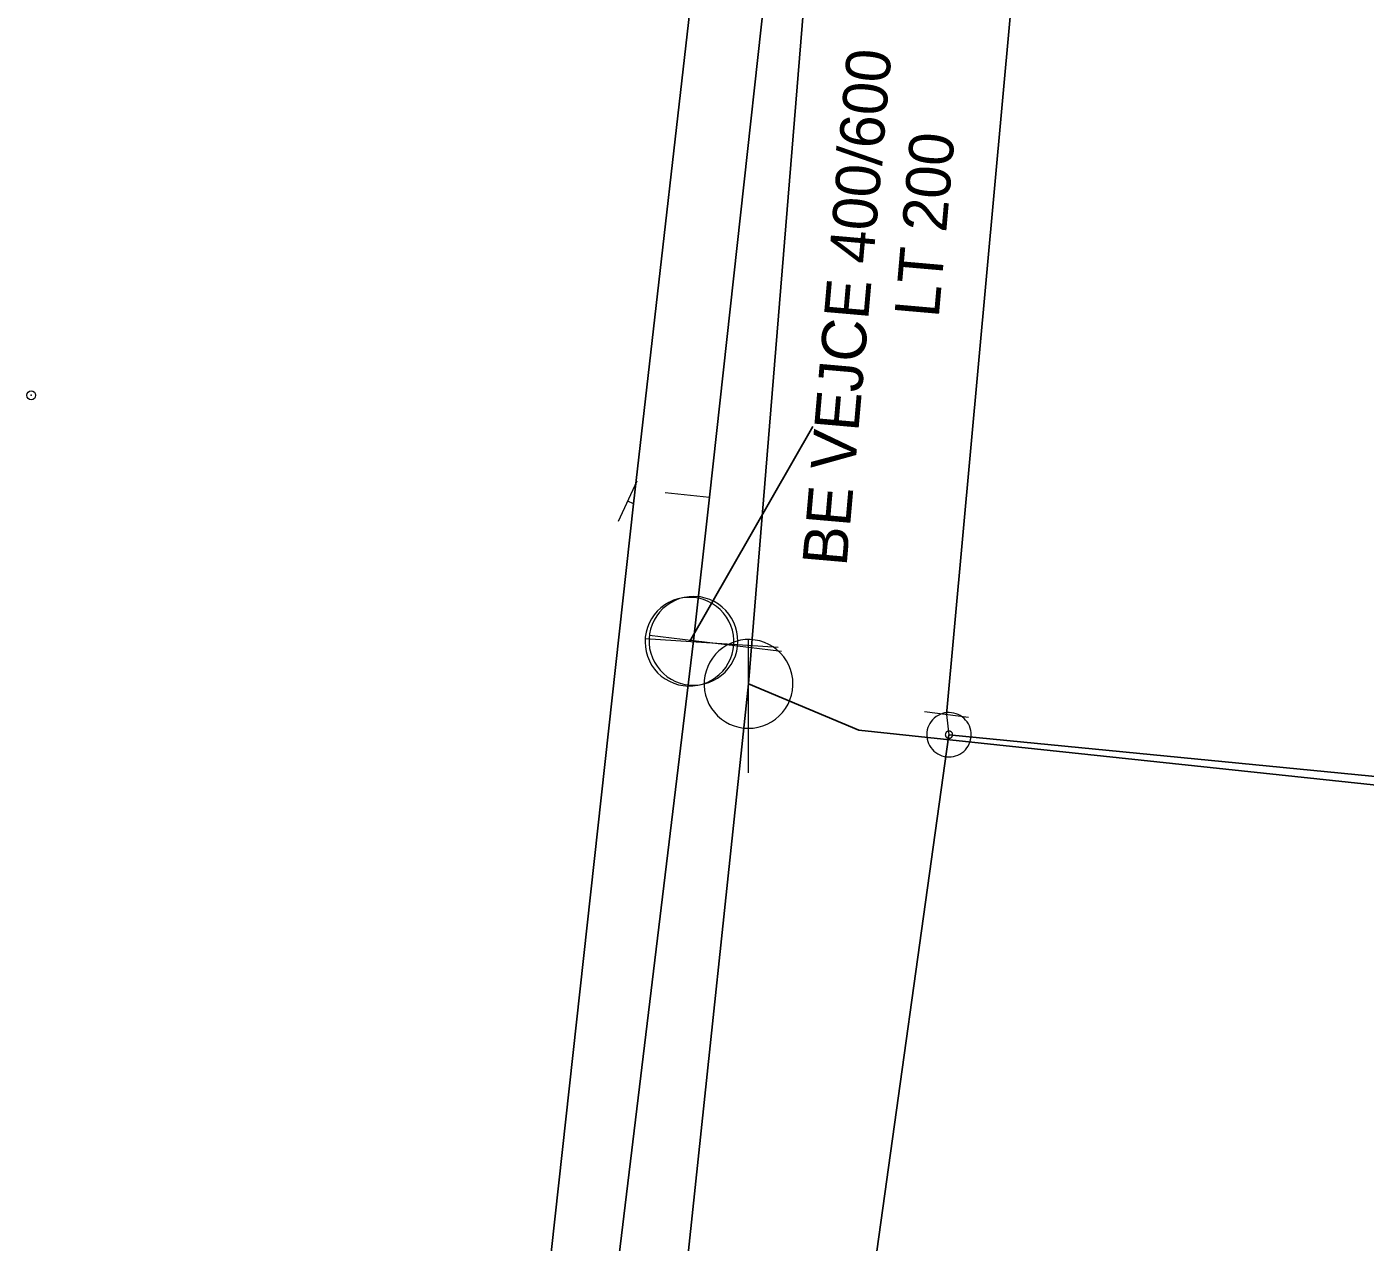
# Model space of a CAD drawing. Extents: x -783064 to -782702, y -1007904 to -1007145.
# Drawn here: x -782825.83 to -782795.69, y -1007679.86 to -1007652.48 of the extents above; entities that cross this region are included whole.
import ezdxf

# ---------------------------------------------------------------- set-up
doc = ezdxf.new("R2010")
doc.units = 0
doc.header["$LTSCALE"] = 0.4
doc.header["$PDMODE"] = 32
doc.header["$PDSIZE"] = 0.2
for name, color, linetype, lineweight in [('1', 7, 'Continuous', 13), ('11', 7, 'Continuous', 13), ('14', 7, 'Continuous', 13), ('17', 7, 'Continuous', 25), ('22', 7, 'Continuous', 13), ('34', 7, 'Continuous', 13), ('47', 7, 'Continuous', 13)]:
    doc.layers.add(name, color=color, linetype=linetype, lineweight=lineweight)

msp = doc.modelspace()

# ---------------------------------------------------------------- linework, layer by layer
at = {"layer": '1'}
msp.add_point((-782825.73, -1007660.779), dxfattribs=at)
at = {"layer": '11'}
msp.add_line((-782811.453, -1007662.966), (-782810.458, -1007663.075), dxfattribs=at)
at = {"layer": '14', "lineweight": 25}
for p, q in [((-782809.579, -1007667.28), (-782807.829, -1007645.75)), ((-782810.91, -1007666.33), (-782808.129, -1007661.48)), ((-782813.23, -1007701.83), (-782809.579, -1007667.28))]:
    msp.add_line(p, q, dxfattribs=at)
at = {"layer": '14'}
for p, q in [((-782812.17, -1007663.22), (-782812.3, -1007663.16)), ((-782805.123, -1007667.966), (-782805.066, -1007668.425))]:
    msp.add_line(p, q, dxfattribs=at)
at = {"layer": '14', "lineweight": 25}
for points in [[(-782810.82, -1007666.31), (-782810.458, -1007663.075), (-782808.517, -1007645.371), (-782807.083, -1007632.299), (-782805.767, -1007620.301), (-782805.445, -1007617.359), (-782805.25, -1007615.57)], [(-782815.738, -1007707.013), (-782814.991, -1007700.828), (-782812.932, -1007683.802), (-782810.82, -1007666.31)], [(-782774.75, -1007671.763), (-782807.095, -1007668.323), (-782809.579, -1007667.28)]]:
    msp.add_lwpolyline(points, dxfattribs=at)
at = {"layer": '17'}
for points in [[(-782797.572, -1007594.291), (-782799.44, -1007613.69), (-782801.199, -1007629.14), (-782801.87, -1007634.05), (-782802.967, -1007644.343), (-782805.123, -1007667.966)], [(-782810.57, -1007649.22), (-782812.17, -1007663.22), (-782814.498, -1007684.393), (-782816.41, -1007701.78), (-782817.839, -1007714.615)], [(-782805.066, -1007668.425), (-782817.623, -1007758.521), (-782825.749, -1007784.698)], [(-782702.62, -1007679.29), (-782717.631, -1007677.556), (-782739.403, -1007674.936), (-782743.636, -1007674.53), (-782747.535, -1007674.052), (-782805.066, -1007668.425)]]:
    msp.add_lwpolyline(points, dxfattribs=at)
at = {"layer": '22'}
for p, q in [((-782808.913, -1007666.462), (-782811.907, -1007666.263)), ((-782808.833, -1007666.549), (-782811.812, -1007666.19)), ((-782809.579, -1007669.28), (-782809.578, -1007666.28))]:
    msp.add_line(p, q, dxfattribs=at)
for points in [[(-782810.843, -1007665.332), (-782810.952, -1007665.33), (-782811.061, -1007665.341), (-782811.168, -1007665.364), (-782811.272, -1007665.397), (-782811.372, -1007665.443), (-782811.466, -1007665.499), (-782811.554, -1007665.565), (-782811.633, -1007665.64), (-782811.704, -1007665.723), (-782811.766, -1007665.813), (-782811.817, -1007665.91), (-782811.857, -1007666.013), (-782811.886, -1007666.118), (-782811.903, -1007666.226), (-782811.909, -1007666.336), (-782811.902, -1007666.445), (-782811.884, -1007666.553), (-782811.854, -1007666.658), (-782811.812, -1007666.76), (-782811.76, -1007666.855), (-782811.697, -1007666.946), (-782811.625, -1007667.028), (-782811.544, -1007667.102), (-782811.456, -1007667.167), (-782811.361, -1007667.221), (-782811.261, -1007667.265), (-782811.156, -1007667.298), (-782811.049, -1007667.319), (-782810.939, -1007667.329), (-782810.83, -1007667.326), (-782810.722, -1007667.312), (-782810.616, -1007667.285), (-782810.513, -1007667.248), (-782810.415, -1007667.199), (-782810.323, -1007667.139), (-782810.238, -1007667.071), (-782810.16, -1007666.993), (-782810.093, -1007666.907), (-782810.034, -1007666.815), (-782809.987, -1007666.716), (-782809.95, -1007666.613), (-782809.925, -1007666.506), (-782809.911, -1007666.397), (-782809.91, -1007666.288), (-782809.921, -1007666.179), (-782809.943, -1007666.072), (-782809.977, -1007665.968), (-782810.022, -1007665.867), (-782810.078, -1007665.774), (-782810.144, -1007665.686), (-782810.218, -1007665.606), (-782810.302, -1007665.535), (-782810.392, -1007665.473), (-782810.489, -1007665.422), (-782810.59, -1007665.382), (-782810.697, -1007665.352), (-782810.805, -1007665.335)], [(-782810.699, -1007665.317), (-782810.808, -1007665.31), (-782810.917, -1007665.315), (-782811.026, -1007665.332), (-782811.131, -1007665.359), (-782811.234, -1007665.399), (-782811.331, -1007665.45), (-782811.422, -1007665.512), (-782811.505, -1007665.582), (-782811.581, -1007665.662), (-782811.647, -1007665.748), (-782811.703, -1007665.842), (-782811.749, -1007665.942), (-782811.783, -1007666.046), (-782811.806, -1007666.153), (-782811.818, -1007666.262), (-782811.817, -1007666.371), (-782811.805, -1007666.481), (-782811.78, -1007666.587), (-782811.743, -1007666.69), (-782811.697, -1007666.789), (-782811.639, -1007666.882), (-782811.571, -1007666.968), (-782811.494, -1007667.047), (-782811.41, -1007667.117), (-782811.319, -1007667.176), (-782811.221, -1007667.225), (-782811.118, -1007667.264), (-782811.012, -1007667.29), (-782810.903, -1007667.306), (-782810.794, -1007667.309), (-782810.685, -1007667.301), (-782810.578, -1007667.28), (-782810.473, -1007667.248), (-782810.372, -1007667.205), (-782810.277, -1007667.15), (-782810.189, -1007667.086), (-782810.107, -1007667.012), (-782810.035, -1007666.93), (-782809.972, -1007666.841), (-782809.919, -1007666.745), (-782809.876, -1007666.644), (-782809.845, -1007666.539), (-782809.826, -1007666.43), (-782809.819, -1007666.322), (-782809.824, -1007666.212), (-782809.84, -1007666.104), (-782809.869, -1007665.998), (-782809.909, -1007665.896), (-782809.96, -1007665.799), (-782810.02, -1007665.708), (-782810.091, -1007665.624), (-782810.17, -1007665.549), (-782810.257, -1007665.482), (-782810.351, -1007665.426), (-782810.45, -1007665.38), (-782810.554, -1007665.345), (-782810.661, -1007665.322)], [(-782808.579, -1007667.28), (-782808.584, -1007667.171), (-782808.602, -1007667.063), (-782808.632, -1007666.957), (-782808.672, -1007666.856), (-782808.724, -1007666.759), (-782808.786, -1007666.669), (-782808.858, -1007666.586), (-782808.938, -1007666.512), (-782809.026, -1007666.446), (-782809.12, -1007666.391), (-782809.22, -1007666.346), (-782809.325, -1007666.313), (-782809.432, -1007666.291), (-782809.541, -1007666.281), (-782809.651, -1007666.283), (-782809.759, -1007666.297), (-782809.866, -1007666.322), (-782809.969, -1007666.359), (-782810.067, -1007666.408), (-782810.159, -1007666.466), (-782810.245, -1007666.535), (-782810.322, -1007666.612), (-782810.391, -1007666.698), (-782810.45, -1007666.79), (-782810.498, -1007666.888), (-782810.535, -1007666.991), (-782810.561, -1007667.098), (-782810.575, -1007667.206), (-782810.578, -1007667.316), (-782810.568, -1007667.425), (-782810.547, -1007667.532), (-782810.513, -1007667.636), (-782810.469, -1007667.736), (-782810.414, -1007667.831), (-782810.348, -1007667.919), (-782810.274, -1007667.999), (-782810.191, -1007668.071), (-782810.101, -1007668.133), (-782810.005, -1007668.185), (-782809.903, -1007668.226), (-782809.798, -1007668.256), (-782809.69, -1007668.274), (-782809.58, -1007668.28), (-782809.471, -1007668.274), (-782809.363, -1007668.256), (-782809.258, -1007668.227), (-782809.156, -1007668.186), (-782809.059, -1007668.134), (-782808.969, -1007668.072), (-782808.886, -1007668.001), (-782808.811, -1007667.921), (-782808.746, -1007667.833), (-782808.69, -1007667.739), (-782808.646, -1007667.639), (-782808.612, -1007667.535), (-782808.59, -1007667.427), (-782808.58, -1007667.318)]]:
    msp.add_lwpolyline(points, close=True, dxfattribs=at)
at = {"layer": '34'}
for p, q in [((-782812.509, -1007663.614), (-782812.09, -1007662.706)), ((-782805.619, -1007667.904), (-782804.626, -1007668.028))]:
    msp.add_line(p, q, dxfattribs=at)
at = {"layer": '47'}
for points in [[(-782805.008, -1007667.928), (-782805.06, -1007667.925), (-782805.113, -1007667.927), (-782805.164, -1007667.935), (-782805.215, -1007667.947), (-782805.264, -1007667.966), (-782805.311, -1007667.989), (-782805.355, -1007668.018), (-782805.396, -1007668.05), (-782805.433, -1007668.086), (-782805.467, -1007668.126), (-782805.496, -1007668.17), (-782805.52, -1007668.217), (-782805.539, -1007668.265), (-782805.553, -1007668.316), (-782805.562, -1007668.367), (-782805.565, -1007668.419), (-782805.563, -1007668.472), (-782805.555, -1007668.524), (-782805.543, -1007668.574), (-782805.524, -1007668.623), (-782805.501, -1007668.67), (-782805.472, -1007668.715), (-782805.44, -1007668.756), (-782805.404, -1007668.793), (-782805.364, -1007668.826), (-782805.32, -1007668.855), (-782805.273, -1007668.88), (-782805.225, -1007668.898), (-782805.174, -1007668.912), (-782805.123, -1007668.921), (-782805.071, -1007668.924), (-782805.018, -1007668.922), (-782804.966, -1007668.915), (-782804.916, -1007668.902), (-782804.867, -1007668.883), (-782804.82, -1007668.861), (-782804.775, -1007668.832), (-782804.734, -1007668.8), (-782804.697, -1007668.763), (-782804.664, -1007668.723), (-782804.635, -1007668.679), (-782804.61, -1007668.633), (-782804.592, -1007668.584), (-782804.578, -1007668.533), (-782804.569, -1007668.482), (-782804.566, -1007668.43), (-782804.568, -1007668.377), (-782804.575, -1007668.326), (-782804.588, -1007668.275), (-782804.607, -1007668.226), (-782804.629, -1007668.179), (-782804.658, -1007668.135), (-782804.69, -1007668.094), (-782804.727, -1007668.057), (-782804.767, -1007668.023), (-782804.811, -1007667.994), (-782804.857, -1007667.97), (-782804.906, -1007667.951), (-782804.957, -1007667.937)], [(-782805.056, -1007668.343), (-782805.065, -1007668.342), (-782805.073, -1007668.343), (-782805.081, -1007668.344), (-782805.09, -1007668.346), (-782805.098, -1007668.349), (-782805.106, -1007668.353), (-782805.113, -1007668.358), (-782805.12, -1007668.363), (-782805.126, -1007668.369), (-782805.131, -1007668.376), (-782805.136, -1007668.383), (-782805.14, -1007668.391), (-782805.143, -1007668.398), (-782805.146, -1007668.406), (-782805.147, -1007668.415), (-782805.148, -1007668.424), (-782805.147, -1007668.432), (-782805.146, -1007668.44), (-782805.144, -1007668.449), (-782805.141, -1007668.457), (-782805.137, -1007668.465), (-782805.132, -1007668.472), (-782805.127, -1007668.479), (-782805.121, -1007668.486), (-782805.114, -1007668.49), (-782805.107, -1007668.495), (-782805.099, -1007668.499), (-782805.092, -1007668.502), (-782805.084, -1007668.505), (-782805.075, -1007668.506), (-782805.066, -1007668.507), (-782805.058, -1007668.506), (-782805.05, -1007668.505), (-782805.041, -1007668.503), (-782805.033, -1007668.5), (-782805.026, -1007668.497), (-782805.018, -1007668.491), (-782805.011, -1007668.486), (-782805.004, -1007668.48), (-782805, -1007668.473), (-782804.995, -1007668.466), (-782804.991, -1007668.458), (-782804.988, -1007668.451), (-782804.985, -1007668.443), (-782804.984, -1007668.434), (-782804.983, -1007668.425), (-782804.984, -1007668.417), (-782804.985, -1007668.409), (-782804.987, -1007668.4), (-782804.99, -1007668.392), (-782804.993, -1007668.385), (-782804.999, -1007668.377), (-782805.004, -1007668.37), (-782805.01, -1007668.364), (-782805.017, -1007668.359), (-782805.024, -1007668.354), (-782805.032, -1007668.35), (-782805.039, -1007668.347), (-782805.047, -1007668.344)]]:
    msp.add_lwpolyline(points, close=True, dxfattribs=at)

# ---------------------------------------------------------------- texts
at = {"layer": '1'}
for s, p in [('BE VEJCE 400/600', (-782807.373, -1007664.649)), ('LT 200', (-782805.298, -1007659.052))]:
    msp.add_text(s, height=1, rotation=85, dxfattribs=at).set_placement(p)

doc.saveas('drawing.dxf')
